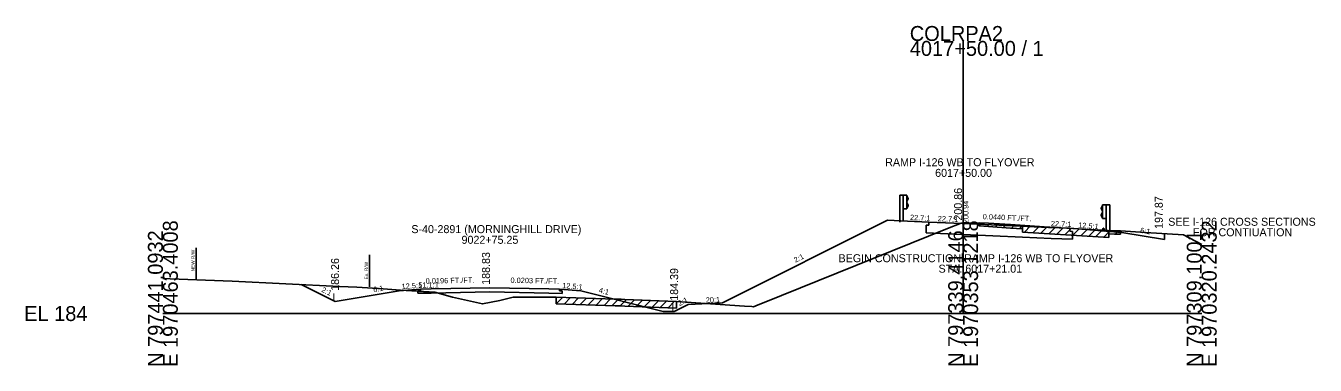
# Model space of a CAD drawing. Extents: x -26 to 1971083, y -10 to 798159.
# Drawn here: x -25.7 to 216, y 1990.3 to 2054 of the extents above; entities that cross this region are included whole.
import ezdxf

# ---------------------------------------------------------------- set-up
doc = ezdxf.new("R2010")
doc.units = 0
for name, color, linetype in [('RD_GPK_XS_Cell', 7, 'Continuous'), ('RD_XS_Base', 7, 'Continuous'), ('RD_XS_CurbTop', 7, 'Continuous'), ('RD_XS_EarthShd', 7, 'Continuous'), ('RD_XS_ExGround', 7, 'Continuous'), ('RD_XS_ExPaveRet', 7, 'Continuous'), ('RD_XS_ExRW', 7, 'Continuous'), ('RD_XS_GR', 7, 'Continuous'), ('RD_XS_Misc_Line', 7, 'Continuous'), ('RD_XS_NewRW', 7, 'Continuous'), ('RD_XS_Pave', 7, 'Continuous'), ('RD_XS_PaveShd', 7, 'Continuous'), ('RD_XS_TieSlope', 7, 'Continuous'), ('RD_XS_TX_Elev_EX', 7, 'Continuous'), ('RD_XS_TX_Elev_PR', 7, 'Continuous'), ('RD_XS_TX_Misc', 7, 'Continuous'), ('RD_XS_TX_MkPT', 7, 'Continuous'), ('RD_XS_TX_Notes', 7, 'Continuous'), ('RD_XS_TX_Profile', 7, 'Continuous'), ('RD_XS_TX_ShdSlope', 7, 'Continuous'), ('RD_XS_TX_Slope', 7, 'Continuous'), ('RD_XS_TX_Station', 7, 'Continuous')]:
    doc.layers.add(name, color=color, linetype=linetype)

msp = doc.modelspace()

# ---------------------------------------------------------------- linework, layer by layer
at = {"layer": 'RD_GPK_XS_Cell'}
for p, q in [((150, 2000), (150, 2051.12)), ((0, 2000), (150, 2000)), ((150, 2000), (194.72, 2000))]:
    msp.add_line(p, q, dxfattribs=at)
at = {"layer": 'RD_XS_Base'}
for p, q in [((143.09, 2016.6), (143.59, 2016.58)), ((143.09, 2015.12), (143.09, 2016.6)), ((143.59, 2016.58), (143.59, 2017.14)), ((170, 2015.98), (170, 2015.98)), ((170, 2015.42), (170, 2015.98)), ((149.8, 2014.83), (143.09, 2015.12)), ((149.8, 2014.83), (150, 2014.82)), ((150, 2014.82), (161.13, 2014.33)), ((166.5, 2014.1), (161.13, 2014.33)), ((166.5, 2014.1), (170.5, 2013.92)), ((170.5, 2015.4), (170, 2015.42)), ((170.5, 2013.92), (170.5, 2015.4)), ((47.79, 2004.27), (48.29, 2004.28)), ((47.79, 2003.79), (47.79, 2004.27)), ((50.29, 2003.84), (47.79, 2003.79)), ((48.29, 2004.28), (48.29, 2004.58)), ((50.29, 2003.84), (61.31, 2004.05)), ((61.31, 2004.05), (72.32, 2003.83)), ((72.32, 2003.83), (74.82, 2003.78)), ((74.32, 2004.27), (74.32, 2004.57)), ((74.82, 2004.26), (74.32, 2004.27)), ((74.82, 2003.78), (74.82, 2004.26))]:
    msp.add_line(p, q, dxfattribs=at)
at = {"layer": 'RD_XS_CurbTop'}
for p, q in [((176, 2015.5), (176.25, 2015.96)), ((176.47, 2015.47), (176.41, 2015.9)), ((176, 2015.5), (176.47, 2015.47))]:
    msp.add_line(p, q, dxfattribs=at)
msp.add_ellipse((176.32, 2015.88), major_axis=(0, -0.131), ratio=0.686, start_param=1.762783, end_param=4.036677, dxfattribs=at)
at = {"layer": 'RD_XS_EarthShd'}
for p, q in [((143.59, 2017.14), (139.59, 2017.32)), ((170, 2015.98), (176, 2015.5)), ((48.29, 2004.58), (44.28, 2004.26)), ((74.32, 2004.57), (78.33, 2004.25))]:
    msp.add_line(p, q, dxfattribs=at)
at = {"layer": 'RD_XS_ExGround'}
msp.add_lwpolyline([(0, 2006.55), (1.35, 2006.5), (13.01, 2006.07), (33.08, 2005.09), (36.36, 2004.95), (41.29, 2004.64), (44.57, 2004.4), (50.97, 2004), (54.3, 2003.04), (59.88, 2001.81), (63.19, 2002.47), (65.63, 2003.07), (68.67, 2003.06), (73.71, 2003.07), (84.79, 2002.71), (85.92, 2002.67), (86.58, 2002.65), (96.29, 2002.27), (108.99, 2001.39), (110.4, 2001.29), (110.73, 2001.27), (111.12, 2001.45), (115.96, 2003.39), (147.06, 2015.96), (149.66, 2016.92), (150, 2016.94), (150.49, 2016.96), (153, 2017.04), (154.77, 2016.93), (158.86, 2016.67), (165.17, 2016.27), (175.87, 2015.62), (176.55, 2015.6), (177.17, 2015.57), (178.37, 2015.53), (179.5, 2015.49), (184.17, 2015.22), (191.3, 2014.78), (194.72, 2012.97)], dxfattribs=at)
at = {"layer": 'RD_XS_ExPaveRet'}
for p, q in [((153, 2016.42), (153, 2017.04)), ((153, 2016.42), (154.77, 2016.3)), ((154.77, 2016.3), (158.86, 2016.04)), ((158.86, 2016.04), (161.13, 2015.9)), ((161.13, 2015.27), (161.13, 2016.52)), ((161.13, 2016.52), (161.13, 2015.9)), ((161.13, 2015.27), (165.17, 2015.02)), ((165.17, 2015.02), (177.28, 2014.29)), ((177.28, 2015.57), (177.28, 2014.29)), ((177.28, 2014.95), (177.28, 2015.57)), ((177.28, 2014.95), (178.37, 2014.91)), ((178.37, 2014.91), (179.5, 2014.87)), ((179.5, 2015.49), (179.5, 2014.87)), ((73.71, 2001.82), (73.71, 2003.07)), ((73.71, 2001.82), (84.79, 2001.46)), ((84.79, 2001.46), (85.92, 2001.42)), ((85.92, 2001.42), (86.58, 2001.4)), ((86.58, 2001.4), (96.29, 2001.02)), ((96.29, 2002.27), (96.29, 2001.02))]:
    msp.add_line(p, q, dxfattribs=at)
at = {"layer": 'RD_XS_ExRW'}
msp.add_line((38.7, 2011.02), (38.7, 2005.02), dxfattribs=at)
at = {"layer": 'RD_XS_GR'}
for p, q in [((138.78, 2022.19), (138.11, 2022.19)), ((138.11, 2022.19), (138.11, 2017.14)), ((139.44, 2022.19), (138.78, 2022.19)), ((138.78, 2022.19), (138.78, 2017.25)), ((139.44, 2019.62), (139.44, 2022.19)), ((139.44, 2022.03), (139.72, 2021.59)), ((139.72, 2021.48), (139.44, 2021.04)), ((139.72, 2020.33), (139.44, 2020.77)), ((139.72, 2021.59), (139.72, 2021.48)), ((139.44, 2019.62), (138.78, 2019.62)), ((139.44, 2019.78), (139.72, 2020.22)), ((139.72, 2020.22), (139.72, 2020.33)), ((176.15, 2020.22), (175.88, 2019.78)), ((175.88, 2019.78), (175.88, 2019.67)), ((175.88, 2019.67), (176.15, 2019.23)), ((175.88, 2018.52), (176.15, 2018.96)), ((175.88, 2018.41), (175.88, 2018.52)), ((176.15, 2017.97), (175.88, 2018.41)), ((176.15, 2020.38), (176.81, 2020.38)), ((176.15, 2017.81), (176.15, 2020.38)), ((176.81, 2020.38), (177.48, 2020.38)), ((176.81, 2020.38), (176.81, 2015.44)), ((177.48, 2020.38), (177.48, 2015.33)), ((176.15, 2017.81), (176.81, 2017.81))]:
    msp.add_line(p, q, dxfattribs=at)
at = {"layer": 'RD_XS_Misc_Line'}
for p, q in [((153, 2016.42), (153.59, 2017)), ((154.51, 2016.32), (155.1, 2016.91)), ((156.02, 2016.22), (156.61, 2016.81)), ((157.53, 2016.13), (158.12, 2016.71)), ((159.04, 2016.03), (159.63, 2016.62)), ((160.55, 2015.94), (161.14, 2016.52)), ((161.47, 2015.25), (162.65, 2016.43)), ((163.07, 2015.15), (164.25, 2016.33)), ((164.57, 2015.06), (165.75, 2016.24)), ((166.07, 2014.97), (167.25, 2016.15)), ((167.57, 2014.88), (168.75, 2016.05)), ((169.07, 2014.78), (170.25, 2015.96)), ((170.57, 2014.69), (171.75, 2015.87)), ((172.07, 2014.6), (173.25, 2015.78)), ((173.57, 2014.51), (174.75, 2015.69)), ((174.87, 2014.43), (176.07, 2015.62)), ((176.36, 2014.34), (177.58, 2015.56)), ((178.49, 2014.9), (179.1, 2015.51)), ((73.71, 2001.82), (74.92, 2003.03)), ((75.21, 2001.77), (76.42, 2002.98)), ((76.71, 2001.72), (77.92, 2002.93)), ((78.21, 2001.67), (79.42, 2002.88)), ((79.71, 2001.63), (80.93, 2002.84)), ((81.22, 2001.58), (82.43, 2002.79)), ((82.72, 2001.53), (83.93, 2002.74)), ((84.22, 2001.48), (85.43, 2002.69)), ((85.72, 2001.43), (86.92, 2002.63)), ((87.22, 2001.37), (88.42, 2002.58)), ((88.72, 2001.32), (89.92, 2002.52)), ((90.22, 2001.26), (91.42, 2002.46)), ((91.72, 2001.2), (92.92, 2002.4)), ((93.22, 2001.14), (94.42, 2002.35)), ((94.72, 2001.08), (95.92, 2002.29))]:
    msp.add_line(p, q, dxfattribs=at)
at = {"layer": 'RD_XS_NewRW'}
msp.add_line((6.23, 2012.32), (6.23, 2006.32), dxfattribs=at)
at = {"layer": 'RD_XS_Pave'}
for p, q in [((149.8, 2016.87), (150, 2016.86)), ((150, 2016.86), (166, 2016.16)), ((50.29, 2004.62), (61.31, 2004.83)), ((61.31, 2004.83), (72.32, 2004.61))]:
    msp.add_line(p, q, dxfattribs=at)
at = {"layer": 'RD_XS_PaveShd'}
for p, q in [((149.8, 2016.87), (143.59, 2017.14)), ((166, 2016.16), (170, 2015.98)), ((50.29, 2004.62), (48.29, 2004.58)), ((72.32, 2004.61), (74.32, 2004.57))]:
    msp.add_line(p, q, dxfattribs=at)
at = {"layer": 'RD_XS_TieSlope'}
for p, q in [((135.84, 2017.48), (104.92, 2002.02)), ((139.59, 2017.32), (135.84, 2017.48)), ((176, 2015.5), (179.75, 2015.2)), ((179.75, 2015.2), (187.75, 2013.87)), ((187.75, 2013.87), (187.75, 2015)), ((32.27, 2002.26), (25.9, 2005.44)), ((44.28, 2004.26), (32.27, 2002.26)), ((78.33, 2004.25), (93.77, 2000.39)), ((98.44, 2001.69), (95.83, 2000.39)), ((98.44, 2001.69), (104.92, 2002.02)), ((93.77, 2000.39), (95.83, 2000.39))]:
    msp.add_line(p, q, dxfattribs=at)

# ---------------------------------------------------------------- texts
at = {"layer": 'RD_GPK_XS_Cell'}
for s, p in [('COLRPA2', (140, 2051.12)), ('4017+50.00 / 1', (140, 2048.32)), ('EL 184', (-26, 1998.6))]:
    msp.add_text(s, height=2.8, dxfattribs=at).set_placement(p)
for s, p in [('E 1970463.4008', (2.8, 1990)), ('E 1970353.1218', (152.8, 1990)), ('E 1970320.2432', (197.52, 1990)), ('N 797441.0932', (0, 1990)), ('N 797339.4146', (150, 1990)), ('N 797309.1001', (194.72, 1990))]:
    msp.add_text(s, height=2.8, rotation=90, dxfattribs=at).set_placement(p)
at = {"layer": 'RD_XS_ExRW'}
msp.add_text('Ex. R/W ', height=0.65, rotation=90, dxfattribs=at).set_placement((38.45, 2006.4))
at = {"layer": 'RD_XS_NewRW'}
msp.add_text('NEW R/W ', height=0.65, rotation=90, dxfattribs=at).set_placement((5.96, 2007.88))
at = {"layer": 'RD_XS_TX_Elev_EX'}
msp.add_text('200.94', height=1, rotation=90, dxfattribs=at).set_placement((151, 2016.94))
at = {"layer": 'RD_XS_TX_Elev_PR'}
for s, p in [(' 200.86', (149.8, 2016.87)), (' 188.83', (61.31, 2004.83))]:
    msp.add_text(s, height=1.5, rotation=90, dxfattribs=at).set_placement(p)
at = {"layer": 'RD_XS_TX_Misc'}
for s, p in [('197.87', (187.42, 2015.87)), ('186.26', (33.02, 2004.26)), ('184.39', (96.58, 2002.39))]:
    msp.add_text(s, height=1.5, rotation=90, dxfattribs=at).set_placement(p)
at = {"layer": 'RD_XS_TX_MkPT'}
for p in [(31.76, 2002.26), (95.32, 2000.39)]:
    msp.add_text('L', height=1.5, dxfattribs=at).set_placement(p)
at = {"layer": 'RD_XS_TX_Notes'}
for s, p in [('SEE I-126 CROSS SECTIONS', (188.44, 2016.46)), ('FOR CONTIUATION', (193.07, 2014.49)), ('BEGIN CONSTRUCTION RAMP I-126 WB TO FLYOVER', (126.65, 2009.62)), ('STA. 6017+21.01', (145.39, 2007.66))]:
    msp.add_text(s, height=1.5, dxfattribs=at).set_placement(p)
at = {"layer": 'RD_XS_TX_Profile'}
msp.add_text('51.1:1', height=1, rotation=1.1205, dxfattribs=at).set_placement((47.9, 2004.82))
at = {"layer": 'RD_XS_TX_ShdSlope'}
for s, rotation, p in [('22.7:1', 357.4806, (140.03, 2017.55)), ('12.5:1', 355.4261, (171.54, 2016.11)), ('12.5:1', 4.5677, (44.79, 2004.55)), ('12.5:1', 355.4323, (74.82, 2004.78))]:
    msp.add_text(s, height=1, rotation=rotation, dxfattribs=at).set_placement(p)
at = {"layer": 'RD_XS_TX_Slope'}
for s, rotation, p in [('22.7:1', 357.4806, (145.23, 2017.32)), ('0.0440 FT./FT.', 357.4889, (153.65, 2017.7)), ('22.7:1', 357.4806, (166.43, 2016.39)), ('6:1', 350.5377, (183.14, 2015.15)), ('2:1', 26.5628, (118.56, 2009.51)), ('0.0196 FT./FT.', 1.1205, (49.27, 2005.6)), ('0.0203 FT./FT.', 358.8352, (65.15, 2005.76)), ('2:1', 333.4664, (29.63, 2004.13)), ('6:1', 9.4496, (39.5, 2003.97)), ('4:1', 345.971, (81.63, 2003.94)), ('2:1', 26.5651, (96.82, 2001.37)), ('20:1', 2.8624, (101.78, 2002.01))]:
    msp.add_text(s, height=1, rotation=rotation, dxfattribs=at).set_placement(p)
at = {"layer": 'RD_XS_TX_Station'}
for s, p in [('RAMP I-126 WB TO FLYOVER', (135.39, 2027.63)), ('6017+50.00', (144.75, 2025.63)), ('S-40-2891 (MORNINGHILL DRIVE)', (46.57, 2015.08)), ('9022+75.25', (55.98, 2013.08))]:
    msp.add_text(s, height=1.5, dxfattribs=at).set_placement(p)

doc.saveas('drawing.dxf')
